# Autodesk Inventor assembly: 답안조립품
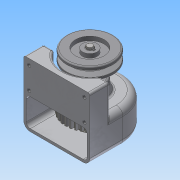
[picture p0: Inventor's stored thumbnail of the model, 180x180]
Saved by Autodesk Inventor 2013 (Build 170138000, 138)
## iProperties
Created: 2015-02
Part Number: 답안조립품
Document SubType Name: Assembly
Designer: Administrator
Author: Administrator
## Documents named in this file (13)
- C:\Documents and Settings\Administrator\바탕 화면\450214v1006\답안조립품.iam
- C:\Documents and Settings\Administrator\바탕 화면\450214v1006\1-본체.ipt
- C:\Documents and Settings\Administrator\바탕 화면\450214v1006\축.ipt
- C:\Documents and Settings\Administrator\바탕 화면\450214v1006\키5x5.ipt
- C:\Documents and Settings\Administrator\바탕 화면\450214v1006\베어링 6001.ipt
- C:\Documents and Settings\Administrator\바탕 화면\450214v1006\축커버.ipt
- C:\Documents and Settings\Administrator\바탕 화면\450214v1006\오일실.ipt
- C:\Documents and Settings\Administrator\바탕 화면\450214v1006\M3x0.5.ipt
- C:\Documents and Settings\Administrator\바탕 화면\450214v1006\4-V-벨트풀리.ipt
- C:\Documents and Settings\Administrator\바탕 화면\450214v1006\키4x4.ipt
- C:\Documents and Settings\Administrator\바탕 화면\450214v1006\M5x0.8.ipt
- M5x0.8.ipt
- C:\Documents and Settings\Administrator\바탕 화면\450214v1006\5-스퍼기어.ipt
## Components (7 placed, 4 different names)
1. 1-본체:1
2. 4-V-벨트풀리:1 — 플러쉬:1, 각도:2
3. M5x0.8:1 — 각도:3
4. M3x0.5:1
5. M3x0.5:2
6. M3x0.5:3
7. M3x0.5:4
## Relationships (3: Angle 2, Flush 1)
- 플러쉬:1 [Flush]: 4-V-벨트풀리:1
- 각도:2 [Angle]: 4-V-벨트풀리:1
- 각도:3 [Angle]: M5x0.8:1
